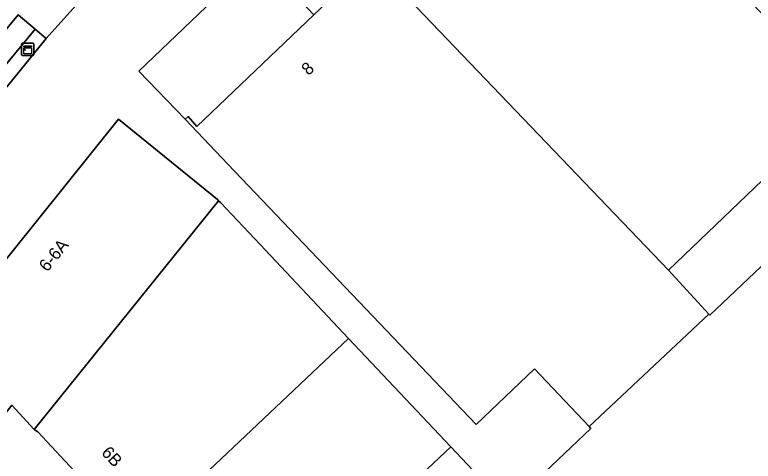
# Model space of a CAD drawing. Extents: x 156702 to 158052, y 387630 to 388992.
# Drawn here: x 157434.5 to 157494.2, y 388126 to 388162.1 of the extents above; entities that cross this region are included whole.
import ezdxf

# ---------------------------------------------------------------- set-up
doc = ezdxf.new("R2010")
doc.units = 0
for name, color, linetype in [('IMGEO_Erf', 7, 'Continuous'), ('IMGEO_Groenvoorziening', 7, 'Continuous'), ('IMGEO_Kast', 7, 'Continuous'), ('IMGEO_Pand', 7, 'Continuous'), ('IMGEO_Pand_nummerreeks', 7, 'Continuous'), ('IMGEO_Pand_overbouw', 7, 'Continuous'), ('IMGEO_Parkeervlak_open', 7, 'Continuous'), ('IMGEO_Voetpad_open', 7, 'Continuous')]:
    doc.layers.add(name, color=color, linetype=linetype)

msp = doc.modelspace()

# ---------------------------------------------------------------- linework, layer by layer
at = {"layer": 'IMGEO_Erf'}
for points in [[(157493.249, 388214.823), (157491.107, 388212.731), (157491.239, 388212.61), (157490.267, 388211.711), (157481.015, 388202.978), (157480.83, 388203.161), (157468.85, 388191.959), (157469.027, 388191.734), (157464.53, 388187.517), (157456.336, 388179.654), (157444.998, 388168.465), (157439.451, 388162.839), (157439.425, 388162.812), (157437.029, 388160.17), (157418.031, 388136.851), (157411.021, 388128.098), (157365.224, 388071.291), (157364.694, 388070.576)], [(157476.28, 388124.152), (157481.047, 388128.674), (157480.905, 388128.823), (157476.493, 388133.467), (157471.791, 388128.979), (157451.715, 388150.016), (157448.263, 388153.633), (157448.493, 388153.846), (157449.204, 388153.057), (157458.673, 388162.071), (157463.312, 388166.487), (157466.344, 388163.359), (157480.637, 388177.073), (157500, 388156.83), (157501.636, 388155.12), (157500, 388153.555), (157487.337, 388141.438), (157490.596, 388137.903), (157490.681, 388137.812), (157500, 388146.653), (157500.108, 388146.755), (157518.703, 388127.151), (157515.079, 388123.707)], [(157439.683, 388124.837), (157436.367, 388128.379), (157436.058, 388128.58), (157434.242, 388130.538), (157432.703, 388128.589), (157432.84, 388128.443), (157432.622, 388128.237), (157428.086, 388133.022), (157428.309, 388133.234), (157428.44, 388133.097), (157429.754, 388135.283), (157432.409, 388139.702), (157431.942, 388140.078), (157432.143, 388140.327), (157442.877, 388153.632), (157450.888, 388147.146), (157450.969, 388147.061), (157451.116, 388146.904), (157454.321, 388143.511), (157461.467, 388135.938), (157469.727, 388127.185), (157486.247, 388109.678)]]:
    msp.add_lwpolyline(points, dxfattribs=at)
at = {"layer": 'IMGEO_Groenvoorziening'}
msp.add_lwpolyline([(157437.029, 388160.17), (157436.133, 388160.9), (157432.913, 388157.037), (157418.073, 388138.591), (157417.202, 388137.538), (157418.031, 388136.851)], close=True, dxfattribs=at)
at = {"layer": 'IMGEO_Kast'}
for p, q in [((157435.037, 388158.862), (157435.037, 388159.703)), ((157435.037, 388159.703), (157435.037, 388158.862)), ((157435.112, 388159.787), (157435.953, 388159.787)), ((157435.953, 388159.787), (157435.112, 388159.787)), ((157436.037, 388159.712), (157436.037, 388158.871)), ((157436.037, 388158.871), (157436.037, 388159.712)), ((157435.962, 388158.787), (157435.121, 388158.787)), ((157435.121, 388158.787), (157435.962, 388158.787))]:
    msp.add_line(p, q, dxfattribs=at)
for points in [[(157435.232, 388159.577), (157435.832, 388159.577), (157435.832, 388159.492), (157435.232, 388159.492), (157435.232, 388159.577)], [(157435.232, 388159.402), (157435.832, 388159.402), (157435.832, 388158.913), (157435.232, 388158.913), (157435.232, 388159.402)]]:
    msp.add_lwpolyline(points, dxfattribs=at)
msp.add_circle((157435.316, 388159.251), 0.0377, dxfattribs=at)
for centre, start, end in [((157435.115, 388159.709), 92.4484, 184.28452), ((157435.115, 388159.709), 92.4484, 184.28452), ((157435.959, 388159.709), 2.4484, 94.28452), ((157435.959, 388159.709), 2.4484, 94.28452), ((157435.115, 388158.865), 182.4484, 274.28452), ((157435.115, 388158.865), 182.4484, 274.28452), ((157435.959, 388158.865), 272.4484, 4.28452), ((157435.959, 388158.865), 272.4484, 4.28452)]:
    msp.add_arc(centre, 0.0779, start, end, dxfattribs=at)
at = {"layer": 'IMGEO_Pand'}
for points in [[(157487.337, 388141.438), (157500, 388153.555), (157501.636, 388155.12), (157500, 388156.83), (157480.637, 388177.073), (157466.344, 388163.359)], [(157487.337, 388141.438), (157466.344, 388163.359), (157463.312, 388166.487), (157458.673, 388162.071), (157449.204, 388153.057), (157448.493, 388153.846), (157448.263, 388153.633), (157451.715, 388150.016), (157471.791, 388128.979), (157476.493, 388133.467), (157480.905, 388128.823), (157490.596, 388137.903)], [(157436.058, 388128.58), (157450.969, 388147.061), (157450.888, 388147.146), (157442.877, 388153.632), (157432.143, 388140.327), (157431.942, 388140.078), (157432.409, 388139.702), (157429.754, 388135.283), (157428.44, 388133.097), (157428.309, 388133.234), (157428.086, 388133.022), (157432.622, 388128.237), (157432.84, 388128.443), (157432.703, 388128.589), (157434.242, 388130.538)], [(157442.354, 388117.905), (157461.467, 388135.938), (157454.321, 388143.511), (157451.116, 388146.904), (157450.969, 388147.061), (157436.058, 388128.58), (157436.367, 388128.379), (157439.683, 388124.837), (157440.601, 388123.856), (157438.565, 388121.923)], [(157480.905, 388128.823), (157481.047, 388128.674), (157476.28, 388124.152), (157476.085, 388123.967), (157494.707, 388104.345), (157500, 388109.376), (157515.079, 388123.707), (157518.703, 388127.151), (157500.108, 388146.755), (157500, 388146.653), (157490.681, 388137.812), (157490.596, 388137.903)], [(157452.656, 388111.088), (157469.727, 388127.185), (157461.467, 388135.938), (157442.354, 388117.905), (157446.173, 388113.855), (157448.181, 388115.748), (157449.174, 388114.787)], [(157452.656, 388111.088), (157456.197, 388107.327), (157457.123, 388106.344), (157455.093, 388104.405), (157462.694, 388096.336), (157464.703, 388098.229), (157465.635, 388097.252), (157469.164, 388093.553), (157486.247, 388109.678), (157469.727, 388127.185)]]:
    msp.add_lwpolyline(points, close=True, dxfattribs=at)
at = {"layer": 'IMGEO_Pand_overbouw'}
msp.add_lwpolyline([(157448.263, 388153.633), (157448.493, 388153.846), (157449.204, 388153.057), (157458.673, 388162.071), (157454.195, 388166.773), (157444.511, 388157.53)], close=True, dxfattribs=at)
at = {"layer": 'IMGEO_Parkeervlak_open'}
msp.add_lwpolyline([(157431.569, 388158.225), (157434.767, 388162.074)], dxfattribs=at)
at = {"layer": 'IMGEO_Voetpad_open'}
msp.add_lwpolyline([(157434.767, 388162.074), (157436.133, 388160.9), (157437.029, 388160.17), (157439.425, 388162.812), (157439.451, 388162.839), (157444.998, 388168.465)], dxfattribs=at)
msp.add_lwpolyline([(157434.767, 388162.074), (157431.569, 388158.225), (157416.657, 388139.726), (157418.073, 388138.591), (157432.913, 388157.037), (157436.133, 388160.9)], close=True, dxfattribs=at)

# ---------------------------------------------------------------- texts
at = {"layer": 'IMGEO_Pand_nummerreeks'}
for s, rotation, p in [('8', 43.61554, (157458.238, 388157.122)), ('6-6A', 51.10435, (157437.131, 388141.252)), ('6B', 313.09989, (157441.432, 388126.655))]:
    msp.add_text(s, height=1, rotation=rotation, dxfattribs=at).set_placement(p)

doc.saveas('drawing.dxf')
